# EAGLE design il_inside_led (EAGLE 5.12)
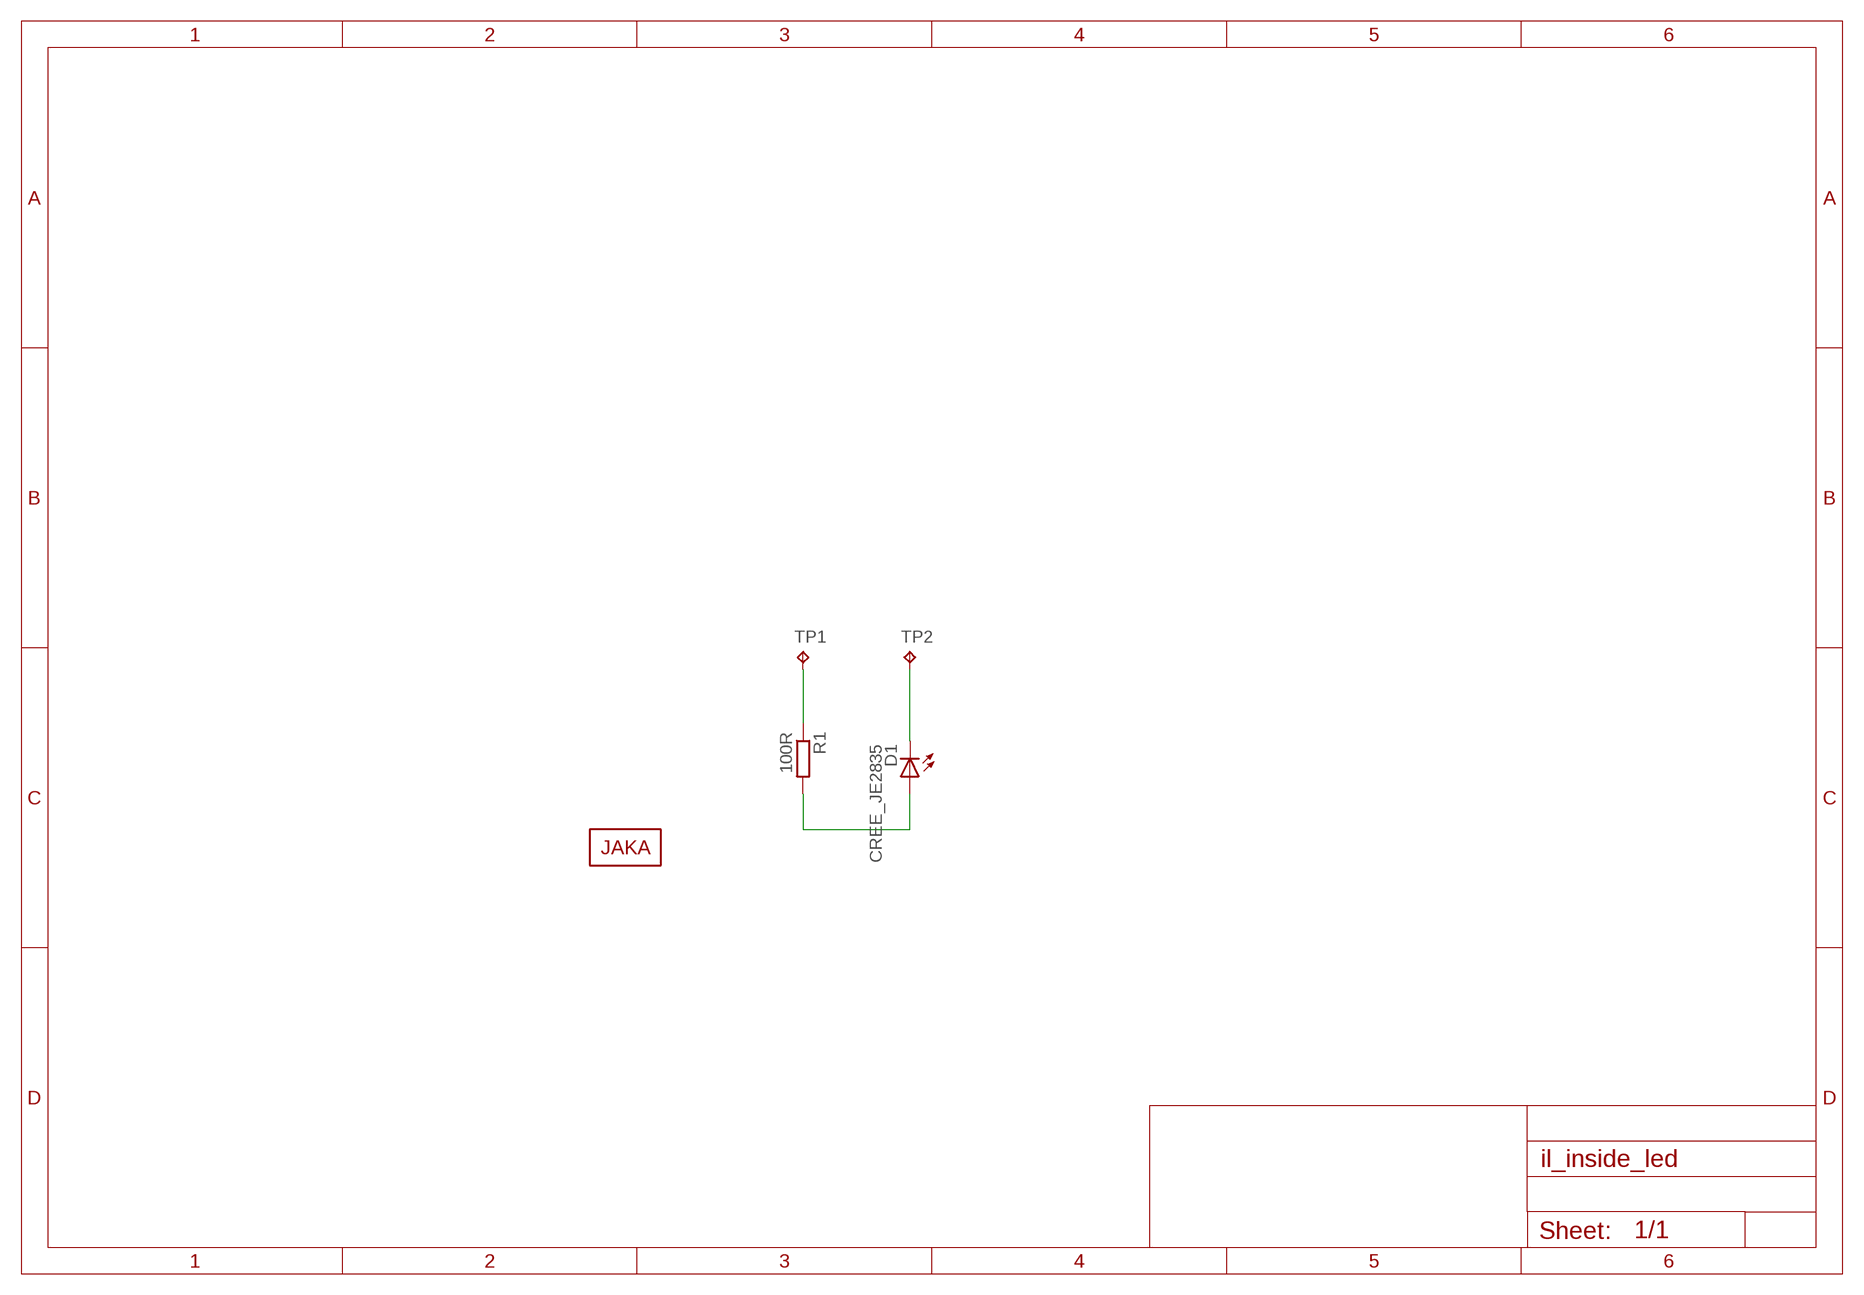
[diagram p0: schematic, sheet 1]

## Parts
D1  CREE_JE2835  [CREE_J2835]
R1  100R  R-EU_R0805  [R0805]
TP1  TESTPOINTTH_1MM  [P1-10]
TP2  TESTPOINTTH_1MM  [P1-10]
U$1  JAKA_LOGO_MASK_NANO  [JAKA_MASK_NANO]

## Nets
N$1: R1.1 TP1.TP
N$2: D1.A R1.2
N$3: D1.K TP2.TP

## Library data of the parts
D1 = omat:CREE_JE2835
R1 = omat:R-EU_: RESISTOR, European symbol
TP1 TP2 = omat:TESTPOINT
U$1 = omat:JAKA_LOGO

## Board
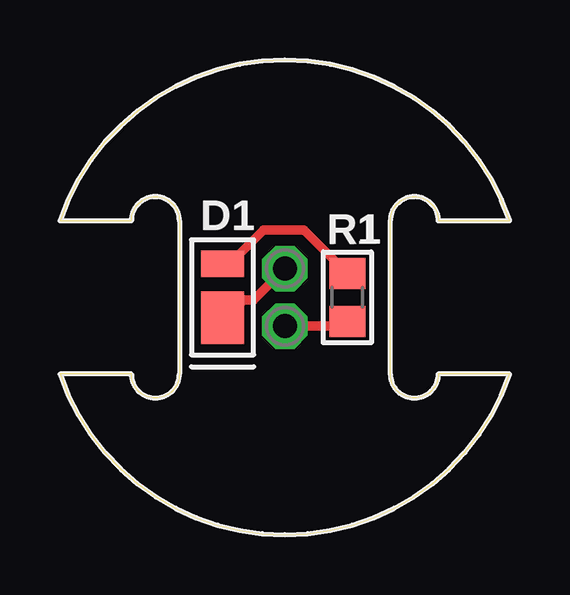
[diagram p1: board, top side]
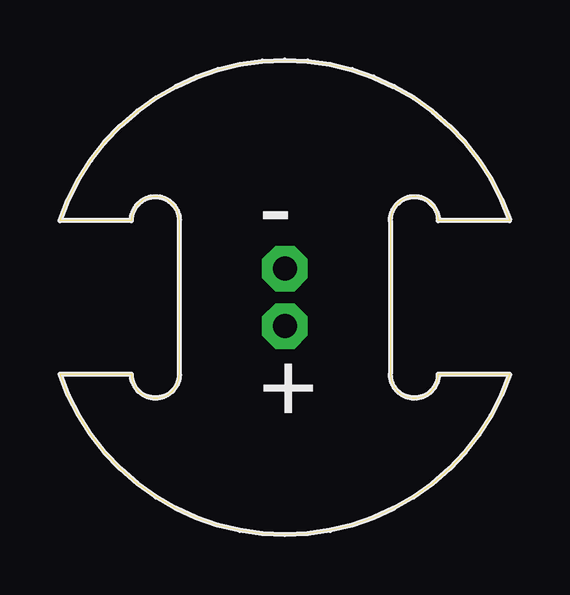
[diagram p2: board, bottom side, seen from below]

Size 18.76 x 19.8 mm. Coordinates in mm from the lower left corner, seen from the top.
Outline: 9.38,0 arc71 18.76,6.7 15.78,6.7 arc-90 14.78,5.7 arc-90 13.78,6.7 13.78,13.1 arc-90 14.78,14.1 arc-90 15.78,13.1 18.76,13.1 arc71 9.38,19.8 arc71 0,13.1 2.98,13.1 arc-90 3.98,14.1 arc-90 4.98,13.1 4.98,6.7 arc-90 3.98,5.7 arc-90 2.98,6.7 0,6.7 arc71 9.38,0
Copper layers (1*16): Top 0.035mm / dielectric 1.5mm / Bottom 0.035mm
Design rules "default": minimum track width 10mil, minimum drill 24mil, track to track 8mil, track to pad 8mil, pad to pad 8mil, via to via 8mil, smd to smd 8mil, copper to edge 40mil, drill to drill 8mil, minimum pad ring 10mil, minimum via ring 8mil, stop-mask expansion 4mil, vias tented up to drill 0mil, thermal gap 10mil

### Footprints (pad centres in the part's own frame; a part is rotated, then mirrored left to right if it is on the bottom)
CREE_J2835 = smd 1.1 x 1.8: A 1.4,0 | smd 2.2 x 1.8: K -0.85,0
R0805 = smd 1.3 x 1.5: 1 -1,0; 2 1,0
P1-10 = drill 1 pad 1.9 octagon: TP 0,0

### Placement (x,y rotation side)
D1  6.78,9.9 90 top
R1  11.98,9.9 90 top
TP1  9.38,8.7 0 top
TP2  9.38,11.1 0 top
U$1  9.28,4.6 0 top

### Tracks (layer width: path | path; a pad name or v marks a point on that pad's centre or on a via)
N$1
  Top 0.4: TP1.TP 11.78,8.7 R1.1
N$2
  Top 0.4: R1.2 10.18,12.7 8.48,12.7 7.08,11.3 D1.A
N$3
  Top 0.4: TP2.TP 8.08,9.8 7.68,9.8 6.93,9.05 D1.K

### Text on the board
bPlace: - | +
tStop: iL | inside LED | 2020
bStop: WWW.KAIR.US
_tsilk: D1 | R1
_bsilk: - | +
